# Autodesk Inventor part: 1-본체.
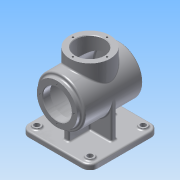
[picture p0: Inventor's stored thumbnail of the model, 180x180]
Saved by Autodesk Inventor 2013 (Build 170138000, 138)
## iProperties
Created: 2015-07
Part Number: 1-본체.
Material: 알루미늄 6061
Document SubType Name: Modeling
Designer: ST1
Density: 2.71 g/cm^3
Mass: 1277.62 g
Surface Area: 1267.64 cm^2
Volume: 471.447 cm^3
Author: ST1
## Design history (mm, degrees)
sketch "스케치1"
  geometry: L1 (0, 0)-(130, 0); L2 (130, 0)-(130, -130); L3 (130, -130)-(0, -130); L4 (0, -130)-(0, 0)
  constraints: 8 end point, 2 parallel, 1 horizontal, 1 perpendicular
  dimensions: "d0" = 130 distance of L1.start L1.end; "d1" = 130 distance of L3.end L1.start
extrude "돌출1" new body sketch "스케치1" distance "d2" = 10; taper "d3" = 0 deg
node "작업 평면1"
sketch "스케치2"
  geometry: L1 (0, 0)-(130, 0) reference; C1 r 45 at (65, 78); 1 further point
  constraints: 1 centre point, 1 midpoint, 1 vertical alignment
  dimensions: "d5" = 78 distance from line of L1 C1.centre; "d6" = 90 diameter of C1
extrude "돌출2" join sketch "스케치2" distance "d7" = 110; taper "d8" = 0 deg
sketch "스케치3"
  geometry: C1 r 45 at (0, 0) reference; C2 r 38 at (0, 0); 1 further point
  constraints: 1 centre point, 1 coincident
  dimensions: "d9" = 76 diameter of C2
extrude "돌출3" join sketch "스케치3" distance "d11" = 7; taper "d12" = 0 deg
sketch "스케치4"
  geometry: C1 r 38 at (0, 0) reference; C2 r 27 at (0, 0); 1 further point
  constraints: 1 centre point, 1 coincident
  dimensions: "d13" = 54 diameter of C2
extrude "돌출4" cut sketch "스케치4" distance "d15" = 14; taper "d16" = 0 deg
sketch "스케치5"
  geometry: C1 r 27 at (0, 0) reference; C2 r 40 at (0, 0); 1 further point
  constraints: 1 centre point, 1 coincident
  dimensions: "d17" = 80 diameter of C2
extrude "돌출5" cut sketch "스케치5" distance "d19" = 96; taper "d20" = 0 deg
node "작업 평면2"
sketch "스케치6"
  geometry: L1 (130, 0)-(0, 0) reference; L2 (110, -10)-(20, -10) reference; C1 r 38 at (65, -65); 1 further point
  constraints: 1 centre point, 1 midpoint, 1 vertical alignment
  dimensions: "d22" = 55 distance from line of L2 C1.centre; "d23" = 76 diameter of C1
extrude "돌출6" join sketch "스케치6" stored distance "d24" = 96; taper "d25" = 0 deg
sketch "스케치7"
  geometry: C1 r 38 at (0, 0) reference; C2 r 27 at (0, 0); 1 further point
  constraints: 1 centre point, 1 coincident
  dimensions: "d26" = 54 diameter of C2
extrude "돌출7" cut sketch "스케치7" stored distance "d28" = 96; taper "d29" = 0 deg
sketch "스케치8" dims "d30" = 64
  geometry: C1 r 27 at (0, 0) reference; C2 r 38 at (0, 0) reference; 3 further points
  constraints: 2 vertical alignment, 1 coincident, 2 other
hole "구멍1" sketch "스케치8" at (0, 32) diameter "d32" = 3.242; stored, may be unused: countersink angle "d36" = 90 deg, drill point angle "d38" = 118 deg; dims "d33" = 8, "d34" = 4, "d35" = 2, "d37" = 10
sketch "스케치9" dims "d42" = 64
  geometry: C1 r 27 at (0, 0) reference; C2 r 38 at (0, 0) reference; 3 further points
  constraints: 2 vertical alignment, 1 coincident, 2 other
hole "구멍2" sketch "스케치9" at (0, 32) diameter "d44" = 3.242; stored, may be unused: countersink angle "d48" = 90 deg, drill point angle "d50" = 118 deg; dims "d45" = 8, "d46" = 4, "d47" = 2, "d49" = 10
fillet "모깎기1" dims "d54" = 3
chamfer "모따기1" distance "d55" = 1; stored, may be unused: second distance "d56" = 2, angle "d57" = 45 deg
fillet "모깎기2" dims "d58" = 15
sketch "스케치10"
  geometry: L1 (0, -15)-(0, -115) reference; L2 (115, 0)-(15, 0) reference; L3 (110, -60)-(110, -70); L4 (20, -70)-(20, -60); L5 (60, -20)-(70, -20); L6 (70, -110)-(60, -110); L7 (20, -60)-(60, -60); L8 (70, -60)-(110, -60); L9 (70, -20)-(70, -60); L10 (70, -70)-(70, -110); L11 (60, -110)-(60, -70); L12 (60, -60)-(60, -20); L13 (110, -70)-(70, -70); L14 (60, -70)-(20, -70); 5 further points
  constraints: 24 end point, 10 parallel, 4 midpoint, 4 perpendicular, 3 horizontal, 3 horizontal alignment, 3 vertical alignment
  dimensions: "d59" = 10 distance of L4.start L4.end; "d61" = 20 distance between parallel lines of L1 L4; "d62" = 90 distance of L3.end L4.start; "d63" = 10 distance of L5.start L5.end; "d64" = 20 distance between parallel lines of L2 L5; "d65" = 90 distance of L6.end L5.start
extrude "돌출8" join sketch "스케치10" stored distance "d66" = 96; taper "d67" = 0 deg
fillet "모깎기3" dims "d68" = 3
fillet "모깎기4" dims "d69" = 3
sketch "스케치11"
  geometry: L1 (0, -15)-(0, -115) reference; L2 (115, 0)-(15, 0) reference; C1 r 7.5 at (15, -15); C2 r 7.5 at (115, -15); C3 r 7.5 at (15, -115); C4 r 7.5 at (115, -115); A1 r 15 centre (15, -15) between (15, 0) and (0, -15) reference; 1 further point
  constraints: 4 centre point, 3 equal radius, 2 horizontal alignment, 2 vertical alignment
  dimensions: "d70" = 15 distance from line of L2 C1.centre; "d71" = 15 distance from line of L1 C1.centre; "d72" = 100 distance of C2.centre A1.centre; "d73" = 100 distance of C3.centre A1.centre; "d74" = 15 diameter of C1
extrude "돌출9" join sketch "스케치11" distance "d75" = 3; taper "d76" = 0 deg
sketch "스케치12"
  geometry: L1 (-100, 15)-(0, 15) reference; L2 (15, 0)-(15, -100) reference; L3 (0, -115)-(-100, -115) reference; L4 (-115, -100)-(-115, 0) reference; C1 r 5 at (-100, 0); C2 r 5 at (0, 0); C3 r 5 at (0, -100); C4 r 5 at (-100, -100); A1 r 15 centre (-100, 0) between (-100, 15) and (-115, 0) reference; A2 r 15 centre (0, 0) between (15, 0) and (0, 15) reference; A3 r 15 centre (0, -100) between (0, -115) and (15, -100) reference; A4 r 15 centre (-100, -100) between (-115, -100) and (-100, -115) reference; 1 further point
  constraints: 4 centre point, 4 coincident, 3 equal radius
  dimensions: "d77" = 10 diameter of C4
extrude "돌출10" cut sketch "스케치12" stored distance "d79" = 3; taper "d80" = 0 deg
fillet "모깎기5" dims "d81" = 3
sketch "스케치13"
  geometry: C1 r 42 at (0, 0) reference; 2 further points
  constraints: 1 coincident, 1 other
feature "엠보싱1" sketch "스케치13" dims "d0" = 130, "d1" = 130, "d82" = 0.5, "d83" = 0
node "솔리드1"
pattern_circular "원형 패턴1" dims angle "d40" = 360 deg
pattern_circular "원형 패턴2" dims angle "d52" = 360 deg
node "투영된 루프1"
